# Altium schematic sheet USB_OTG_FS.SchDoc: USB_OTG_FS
size A4; DocumentNumber: MB1165; Revision: C.1; SheetNumber: 9; SheetTotal: 17; Project: STM32469I-EVAL
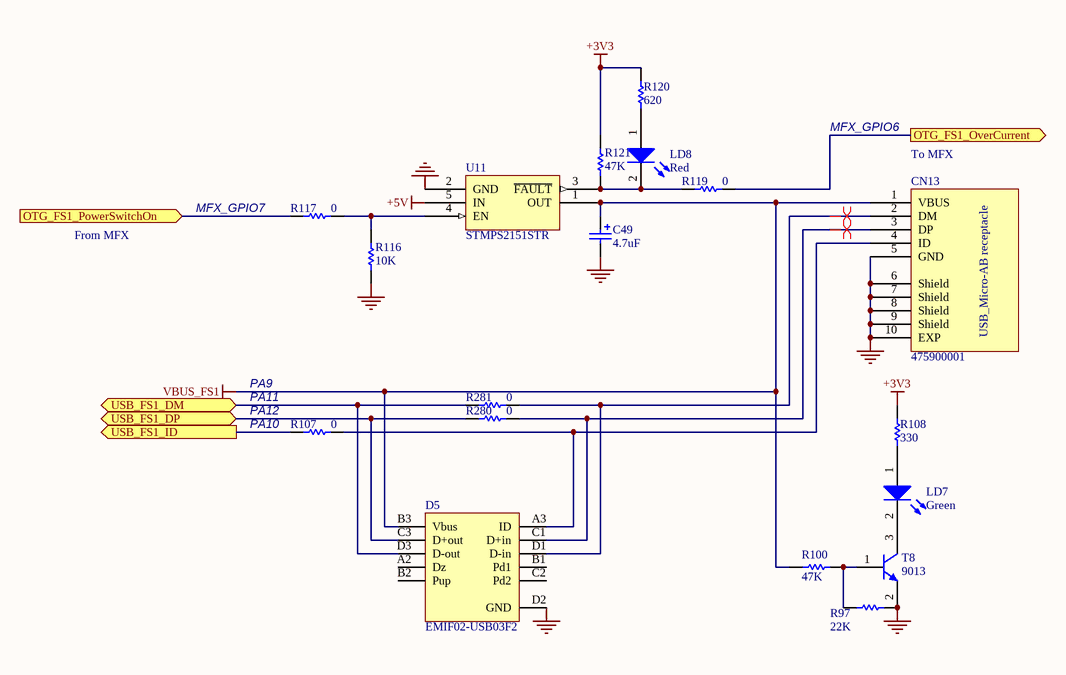
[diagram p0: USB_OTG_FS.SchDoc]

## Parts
C49  4.7uF  [TAN-A]
CN13  475900001  [MOLEX_47590001]
D5  EMIF02-USB03F2  [BGA11_0R5_1R57X2R07]
LD7  Green  [0603D]
LD8  Red  [0603D]
R97  22K  [0603R]
R100  47K  [0603R]
R107  0  [0603R]
R108  330  [0603R]
R116  10K  [0603R]
R117  0  [0603R]
R119  0  [0603R]
R120  620  [0603R]
R121  47K  [0603R]
R280  0  [0603R]
R281  0  [0603R]
T8  9013  [SOT-23]
U11  STMPS2151STR  [SOT23-5]

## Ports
OTG_FS1_OverCurrent (out), OTG_FS1_PowerSwitchOn (in), USB_FS1_DM (bidir), USB_FS1_DP (bidir), USB_FS1_ID (out)

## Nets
+3V3: R108.2 R120.2 R121.1
+5V: U11.5(IN)
GND: C49.2 CN13.5(GND) CN13.6(Shield) CN13.7(Shield) CN13.8(Shield) CN13.9(Shield) CN13.10(EXP) D5.D2(GND) R97.1 R116.1 T8.2(E) U11.2(GND)
VBUS_FS1: C49.1 CN13.1(VBUS) D5.B3(Vbus) R100.1 U11.1(OUT)
OTG_FS1_OverCurrent: R119.1 ; port OTG_FS1_OverCurrent
OTG_FS1_PowerSwitchOn: R117.2 ; port OTG_FS1_PowerSwitchOn
USB_FS1_DM: D5.D3(D-out) R281.2 ; port USB_FS1_DM
USB_FS1_DP: D5.C3(D+out) R280.2 ; port USB_FS1_DP
USB_FS1_ID: R107.2 ; port USB_FS1_ID
NetCN13_2: CN13.2(DM) D5.D1(D-in) R281.1
NetCN13_3: CN13.3(DP) D5.C1(D+in) R280.1
NetCN13_4: CN13.4(ID) D5.A3(ID) R107.1
NetLD7_1: LD7.1(A) R108.1
NetLD7_2: LD7.2(K) T8.3(C)
NetLD8_1: LD8.1(A) R120.1
NetLD8_2: LD8.2(K) R119.2 R121.2 U11.3(~{FAULT})
NetR97_2: R97.2 R100.2 T8.1(B)
NetR116_2: R116.2 R117.1 U11.4(EN)

Not connected (* = marked no-connect by the designer): D5 A2(Dz) B1(Pd1) B2(Pup) C2(Pd2)

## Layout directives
differential pair: NetCN13_2, NetCN13_3

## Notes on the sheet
- MFX_GPIO6
- (near R117) MFX_GPIO7
- (near CN13) To MFX
- From MFX
- PA9
- (near R107) PA11
- (near R107) PA12
- (near R107) PA10

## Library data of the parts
C49 = Cap Pol1: Polarized Capacitor (Radial); Value: 47uF
LD7 LD8 = LED2: Typical RED, GREEN, YELLOW, AMBER GaAs LED
R97 R100 R108 R121 = res1: Resistor; Value: 1K
R107 R116 R117 R119 R120 R280 R281 = Res1: Resistor; Value: 1K
T8 = NPN: NPN Bipolar Transistor; Code - JEDEC: TO-226-AA
U11 = STMPS2141STR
